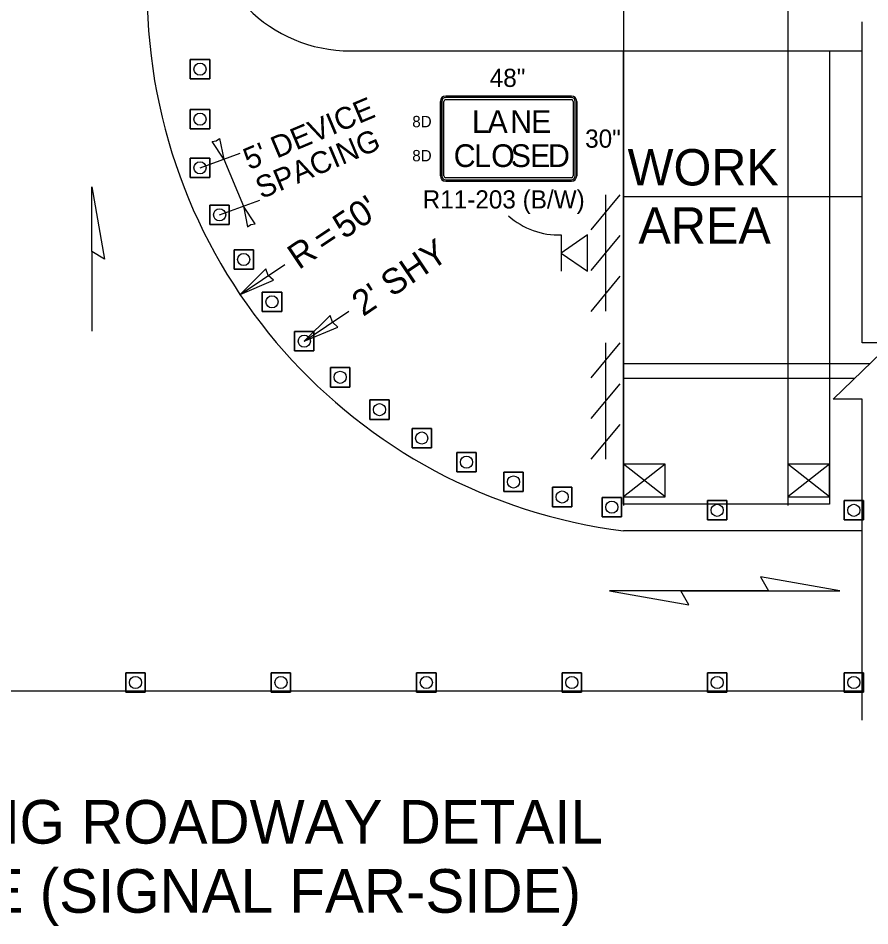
# Model space of a CAD drawing. Extents: x 99979.8 to 100075.7, y 99995 to 100010.7.
# Drawn here: x 100048.053 to 100050.396, y 100006.124 to 100008.621 of the extents above; entities that cross this region are included whole.
import ezdxf

# ---------------------------------------------------------------- set-up
doc = ezdxf.new("R2010")
doc.units = 0
for name, color, linetype in [('RD_ED_ShoulderPavedEdge', 7, 'Continuous'), ('RD_MK_LineDblYellowCenter', 7, 'Continuous'), ('RD_MK_LineEdgeWhite', 7, 'Continuous'), ('RD_MK_LineEdgeWhiteNew', 7, 'Continuous'), ('SH_DE_DetailHeading2Text', 7, 'Continuous'), ('TR_SN_ConstructionSigns', 7, 'Continuous'), ('TR_WZ_BarricadeType3', 7, 'Continuous'), ('TR_WZ_PortableSignMount5ftMinBlk-Wht', 7, 'Continuous'), ('TR_WZ_PortableSignMountBlk-Wht', 7, 'Continuous'), ('TR_WZ_TrafficCone', 7, 'Continuous'), ('TR_WZ_WorkAreaLabel', 7, 'Continuous'), ('TR_WZ_WorkZoneDetails', 7, 'Continuous'), ('TR_WZ_WorkZoneTextCurrent', 7, 'Continuous')]:
    doc.layers.add(name, color=color, linetype=linetype)

msp = doc.modelspace()

# ---------------------------------------------------------------- linework, layer by layer
at = {"layer": 'RD_ED_ShoulderPavedEdge'}
for p, q in [((100048.9675, 100008.5305), (100050.375, 100008.5305)), ((100045.375, 100006.7704), (100050.375, 100006.7704))]:
    msp.add_line(p, q, dxfattribs=at)
msp.add_arc((100048.9675, 100008.9304), 0.4, 180, 270, dxfattribs=at)
at = {"layer": 'RD_MK_LineDblYellowCenter'}
for p, q in [((100049.7179, 100007.6704), (100050.3957, 100007.6704)), ((100049.7179, 100007.6305), (100050.3543, 100007.6305))]:
    msp.add_line(p, q, dxfattribs=at)
at = {"layer": 'RD_MK_LineEdgeWhite'}
for p, q in [((100049.7179, 100008.1305), (100050.375, 100008.1305)), ((100050.375, 100007.2105), (100049.7179, 100007.2105))]:
    msp.add_line(p, q, dxfattribs=at)
at = {"layer": 'RD_MK_LineEdgeWhiteNew'}
msp.add_arc((100049.9075, 100008.6984), 1.5, 180.3046, 262.7399, dxfattribs=at)
at = {"layer": 'TR_SN_ConstructionSigns'}
for p, q in [((100049.229, 100008.4064), (100049.5747, 100008.4064)), ((100049.5747, 100008.4064), (100049.229, 100008.4064)), ((100049.5747, 100008.4064), (100049.229, 100008.4064)), ((100049.5747, 100008.4025), (100049.229, 100008.4025)), ((100049.2144, 100008.1867), (100049.2144, 100008.3918)), ((100049.2144, 100008.3918), (100049.2144, 100008.1867)), ((100049.2144, 100008.3918), (100049.2144, 100008.1867)), ((100049.2183, 100008.3918), (100049.2183, 100008.1867)), ((100049.2241, 100008.1867), (100049.2241, 100008.3918)), ((100049.229, 100008.3967), (100049.5747, 100008.3967)), ((100049.5796, 100008.3918), (100049.5796, 100008.1867)), ((100049.5855, 100008.1867), (100049.5855, 100008.3918)), ((100049.5894, 100008.3918), (100049.5894, 100008.1867)), ((100049.5894, 100008.1867), (100049.5894, 100008.3918)), ((100049.5894, 100008.1867), (100049.5894, 100008.3918)), ((100049.5747, 100008.1818), (100049.229, 100008.1818)), ((100049.229, 100008.176), (100049.5747, 100008.176)), ((100049.5747, 100008.1721), (100049.229, 100008.1721)), ((100049.229, 100008.1721), (100049.5747, 100008.1721)), ((100049.229, 100008.1721), (100049.5747, 100008.1721))]:
    msp.add_line(p, q, dxfattribs=at)
for centre, radius, start, end in [((100049.229, 100008.3918), 0.0146, 90, 180), ((100049.229, 100008.3918), 0.0146, 90, 180), ((100049.229, 100008.3918), 0.0146, 90, 180), ((100049.229, 100008.3918), 0.0107, 90, 180), ((100049.5747, 100008.3918), 0.0146, 0, 90), ((100049.5747, 100008.3918), 0.0146, 0, 90), ((100049.5747, 100008.3918), 0.0146, 0, 90), ((100049.5747, 100008.3918), 0.0107, 0, 90), ((100049.229, 100008.3918), 0.00488, 90, 180), ((100049.5747, 100008.3918), 0.00488, 0, 90), ((100049.229, 100008.1867), 0.0146, 180, 270), ((100049.229, 100008.1867), 0.0146, 180, 270), ((100049.229, 100008.1867), 0.0146, 180, 270), ((100049.229, 100008.1867), 0.0107, 180, 270), ((100049.229, 100008.1867), 0.00488, 180, 270), ((100049.5747, 100008.1867), 0.0107, 270, 0), ((100049.5747, 100008.1867), 0.00488, 270, 0), ((100049.5747, 100008.1867), 0.0146, 270, 0), ((100049.5747, 100008.1867), 0.0146, 270, 0), ((100049.5747, 100008.1867), 0.0146, 270, 0)]:
    msp.add_arc(centre, radius, start, end, dxfattribs=at)
at = {"layer": 'TR_WZ_BarricadeType3'}
for p, q in [((100049.6287, 100008.0385), (100049.7087, 100008.135)), ((100049.6687, 100008.1345), (100049.6687, 100007.8145)), ((100049.6287, 100007.9263), (100049.7087, 100008.0228)), ((100049.6287, 100007.8141), (100049.7087, 100007.9106)), ((100049.6294, 100007.6318), (100049.7087, 100007.7273)), ((100049.669, 100007.7273), (100049.669, 100007.4073)), ((100049.6294, 100007.5195), (100049.7087, 100007.6151)), ((100049.6294, 100007.4073), (100049.7087, 100007.5029))]:
    msp.add_line(p, q, dxfattribs=at)
at = {"layer": 'TR_WZ_PortableSignMount5ftMinBlk-Wht'}
for p, q in [((100049.7179, 100007.4184), (100049.7179, 100007.2805)), ((100050.17, 100007.4184), (100050.17, 100007.2805)), ((100049.833, 100007.3046), (100049.7179, 100007.3942)), ((100049.833, 100007.3942), (100049.7179, 100007.3046)), ((100050.285, 100007.3046), (100050.17, 100007.3942)), ((100050.285, 100007.3942), (100050.17, 100007.3046)), ((100049.7755, 100007.3494), (100049.7755, 100007.3494)), ((100049.7756, 100007.3493), (100049.7756, 100007.3493)), ((100050.2275, 100007.3494), (100050.2275, 100007.3494)), ((100050.2277, 100007.3493), (100050.2277, 100007.3493))]:
    msp.add_line(p, q, dxfattribs=at)
for points in [[(100049.833, 100007.3046), (100049.833, 100007.3942), (100049.7179, 100007.3942), (100049.7179, 100007.3046)], [(100050.285, 100007.3046), (100050.285, 100007.3942), (100050.17, 100007.3942), (100050.17, 100007.3046)]]:
    msp.add_lwpolyline(points, close=True, dxfattribs=at)
at = {"layer": 'TR_WZ_PortableSignMountBlk-Wht'}
msp.add_line((100049.5469, 100008.0245), (100049.5469, 100007.9245), dxfattribs=at)
msp.add_lwpolyline([(100049.5469, 100007.9746), (100049.6187, 100007.9245), (100049.6187, 100008.0245)], close=True, dxfattribs=at)
at = {"layer": 'TR_WZ_TrafficCone'}
for points in [[(100048.5798, 100008.5068), (100048.5264, 100008.5068), (100048.5264, 100008.4535), (100048.5798, 100008.4535), (100048.5798, 100008.5068)], [(100048.5798, 100008.4535), (100048.5264, 100008.4535), (100048.5264, 100008.5068), (100048.5798, 100008.5068), (100048.5798, 100008.4535)], [(100048.5798, 100008.3696), (100048.5264, 100008.3696), (100048.5264, 100008.3163), (100048.5798, 100008.3163), (100048.5798, 100008.3696)], [(100048.5798, 100008.3163), (100048.5264, 100008.3163), (100048.5264, 100008.3696), (100048.5798, 100008.3696), (100048.5798, 100008.3163)], [(100048.5798, 100008.2358), (100048.5264, 100008.2358), (100048.5264, 100008.1825), (100048.5798, 100008.1825), (100048.5798, 100008.2358)], [(100048.5798, 100008.1825), (100048.5264, 100008.1825), (100048.5264, 100008.2358), (100048.5798, 100008.2358), (100048.5798, 100008.1825)], [(100048.6337, 100008.1066), (100048.5804, 100008.1066), (100048.5804, 100008.0532), (100048.6337, 100008.0532), (100048.6337, 100008.1066)], [(100048.6337, 100008.0532), (100048.5804, 100008.0532), (100048.5804, 100008.1066), (100048.6337, 100008.1066), (100048.6337, 100008.0532)], [(100048.6999, 100007.9832), (100048.6466, 100007.9832), (100048.6466, 100007.9299), (100048.6999, 100007.9299), (100048.6999, 100007.9832)], [(100048.6999, 100007.9299), (100048.6466, 100007.9299), (100048.6466, 100007.9832), (100048.6999, 100007.9832), (100048.6999, 100007.9299)], [(100048.7778, 100007.8669), (100048.7244, 100007.8669), (100048.7244, 100007.8136), (100048.7778, 100007.8136), (100048.7778, 100007.8669)], [(100048.7778, 100007.8136), (100048.7244, 100007.8136), (100048.7244, 100007.8669), (100048.7778, 100007.8669), (100048.7778, 100007.8136)], [(100048.8666, 100007.7587), (100048.8132, 100007.7587), (100048.8132, 100007.7053), (100048.8666, 100007.7053), (100048.8666, 100007.7587)], [(100048.8666, 100007.7053), (100048.8132, 100007.7053), (100048.8132, 100007.7587), (100048.8666, 100007.7587), (100048.8666, 100007.7053)], [(100048.9655, 100007.6596), (100048.9121, 100007.6596), (100048.9121, 100007.6062), (100048.9655, 100007.6062), (100048.9655, 100007.6596)], [(100048.9655, 100007.6062), (100048.9121, 100007.6062), (100048.9121, 100007.6596), (100048.9655, 100007.6596), (100048.9655, 100007.6062)], [(100049.0735, 100007.5705), (100049.0202, 100007.5705), (100049.0202, 100007.5172), (100049.0735, 100007.5172), (100049.0735, 100007.5705)], [(100049.0735, 100007.5172), (100049.0202, 100007.5172), (100049.0202, 100007.5705), (100049.0735, 100007.5705), (100049.0735, 100007.5172)], [(100049.1897, 100007.4924), (100049.1364, 100007.4924), (100049.1364, 100007.4391), (100049.1897, 100007.4391), (100049.1897, 100007.4924)], [(100049.1897, 100007.4391), (100049.1364, 100007.4391), (100049.1364, 100007.4924), (100049.1897, 100007.4924), (100049.1897, 100007.4391)], [(100049.3129, 100007.426), (100049.2596, 100007.426), (100049.2596, 100007.3726), (100049.3129, 100007.3726), (100049.3129, 100007.426)], [(100049.3129, 100007.3726), (100049.2596, 100007.3726), (100049.2596, 100007.426), (100049.3129, 100007.426), (100049.3129, 100007.3726)], [(100049.442, 100007.3718), (100049.3887, 100007.3718), (100049.3887, 100007.3184), (100049.442, 100007.3184), (100049.442, 100007.3718)], [(100049.442, 100007.3184), (100049.3887, 100007.3184), (100049.3887, 100007.3718), (100049.442, 100007.3718), (100049.442, 100007.3184)], [(100049.5757, 100007.3304), (100049.5224, 100007.3304), (100049.5224, 100007.2771), (100049.5757, 100007.2771), (100049.5757, 100007.3304)], [(100049.5757, 100007.2771), (100049.5224, 100007.2771), (100049.5224, 100007.3304), (100049.5757, 100007.3304), (100049.5757, 100007.2771)], [(100049.7129, 100007.3022), (100049.6595, 100007.3022), (100049.6595, 100007.2489), (100049.7129, 100007.2489), (100049.7129, 100007.3022)], [(100049.7129, 100007.2489), (100049.6595, 100007.2489), (100049.6595, 100007.3022), (100049.7129, 100007.3022), (100049.7129, 100007.2489)], [(100049.949, 100007.2938), (100050.0023, 100007.2938), (100050.0023, 100007.2405), (100049.949, 100007.2405), (100049.949, 100007.2938)], [(100049.949, 100007.2405), (100050.0023, 100007.2405), (100050.0023, 100007.2938), (100049.949, 100007.2938), (100049.949, 100007.2405)], [(100050.325, 100007.2938), (100050.3783, 100007.2938), (100050.3783, 100007.2405), (100050.325, 100007.2405), (100050.325, 100007.2938)], [(100050.325, 100007.2405), (100050.3783, 100007.2405), (100050.3783, 100007.2938), (100050.325, 100007.2938), (100050.325, 100007.2405)], [(100048.349, 100006.8204), (100048.4023, 100006.8204), (100048.4023, 100006.7671), (100048.349, 100006.7671), (100048.349, 100006.8204)], [(100048.349, 100006.7671), (100048.4023, 100006.7671), (100048.4023, 100006.8204), (100048.349, 100006.8204), (100048.349, 100006.7671)], [(100048.749, 100006.8204), (100048.8023, 100006.8204), (100048.8023, 100006.7671), (100048.749, 100006.7671), (100048.749, 100006.8204)], [(100048.749, 100006.7671), (100048.8023, 100006.7671), (100048.8023, 100006.8204), (100048.749, 100006.8204), (100048.749, 100006.7671)], [(100049.149, 100006.8204), (100049.2023, 100006.8204), (100049.2023, 100006.7671), (100049.149, 100006.7671), (100049.149, 100006.8204)], [(100049.149, 100006.7671), (100049.2023, 100006.7671), (100049.2023, 100006.8204), (100049.149, 100006.8204), (100049.149, 100006.7671)], [(100049.549, 100006.8204), (100049.6023, 100006.8204), (100049.6023, 100006.7671), (100049.549, 100006.7671), (100049.549, 100006.8204)], [(100049.549, 100006.7671), (100049.6023, 100006.7671), (100049.6023, 100006.8204), (100049.549, 100006.8204), (100049.549, 100006.7671)], [(100049.949, 100006.8204), (100050.0023, 100006.8204), (100050.0023, 100006.7671), (100049.949, 100006.7671), (100049.949, 100006.8204)], [(100049.949, 100006.7671), (100050.0023, 100006.7671), (100050.0023, 100006.8204), (100049.949, 100006.8204), (100049.949, 100006.7671)], [(100050.325, 100006.8204), (100050.3783, 100006.8204), (100050.3783, 100006.7671), (100050.325, 100006.7671), (100050.325, 100006.8204)], [(100050.325, 100006.7671), (100050.3783, 100006.7671), (100050.3783, 100006.8204), (100050.325, 100006.8204), (100050.325, 100006.7671)]]:
    msp.add_lwpolyline(points, dxfattribs=at)
for centre in [(100048.5531, 100008.4801), (100048.5531, 100008.3429), (100048.5531, 100008.2091), (100048.607, 100008.0799), (100048.6732, 100007.9566), (100048.7511, 100007.8402), (100048.8399, 100007.732), (100048.9388, 100007.6329), (100049.0468, 100007.5439), (100049.163, 100007.4658), (100049.2862, 100007.3993), (100049.4153, 100007.3451), (100049.5491, 100007.3037), (100049.6862, 100007.2755), (100049.9757, 100007.2671), (100050.3517, 100007.2671), (100048.3757, 100006.7938), (100048.7757, 100006.7938), (100049.1757, 100006.7938), (100049.5757, 100006.7938), (100049.9757, 100006.7938), (100050.3517, 100006.7938)]:
    msp.add_circle(centre, 0.0167, dxfattribs=at)
at = {"layer": 'TR_WZ_WorkZoneDetails'}
for p, q in [((100049.7179, 100008.6504), (100049.7179, 100007.4184)), ((100050.17, 100008.6504), (100050.17, 100007.4184)), ((100048.5532, 100008.2091), (100048.6637, 100008.249)), ((100048.6184, 100008.2327), (100048.6723, 100008.1035)), ((100048.6071, 100008.0799), (100048.7176, 100008.1198)), ((100048.2552, 100007.9784), (100048.2552, 100007.7594)), ((100048.6632, 100007.8606), (100048.786, 100007.9433)), ((100048.8399, 100007.7319), (100048.9628, 100007.8146)), ((100050.117, 100007.0455), (100049.8759, 100007.0455)), ((100049.8759, 100007.0455), (100050.117, 100007.0455))]:
    msp.add_line(p, q, dxfattribs=at)
msp.add_lwpolyline([(100050.375, 100006.6904), (100050.375, 100007.573), (100050.295, 100007.573), (100050.455, 100007.7279), (100050.375, 100007.7279), (100050.375, 100008.6105)], dxfattribs=at)
for points in [[(100050.285, 100008.5305), (100050.285, 100007.2838), (100049.7179, 100007.2838), (100049.7179, 100007.2838), (100049.7179, 100007.2838), (100049.7179, 100007.2838), (100049.7179, 100007.2838), (100049.7179, 100007.2838), (100049.7179, 100007.2838), (100049.7179, 100007.4226), (100049.7179, 100007.5672), (100049.7179, 100007.732), (100049.7179, 100007.9566), (100049.7179, 100008.2091), (100049.7179, 100008.5305)], [(100048.6184, 100008.2327), (100048.5861, 100008.2811), (100048.5974, 100008.283), (100048.6068, 100008.2897)], [(100048.2552, 100008.157), (100048.2903, 100007.9582), (100048.2552, 100007.9784)], [(100048.6723, 100008.1035), (100048.684, 100008.0464), (100048.6933, 100008.0532), (100048.7047, 100008.0551)], [(100048.6632, 100007.8606), (100048.7555, 100007.8996), (100048.7409, 100007.913), (100048.7339, 100007.9315)], [(100048.8399, 100007.7319), (100048.9322, 100007.7709), (100048.9177, 100007.7843), (100048.9107, 100007.8028)], [(100050.3136, 100007.0455), (100050.0947, 100007.084), (100050.117, 100007.0455)], [(100049.6794, 100007.0455), (100049.8982, 100007.0069), (100049.8759, 100007.0455)]]:
    msp.add_lwpolyline(points, close=True, dxfattribs=at)
msp.add_arc((100049.5394, 100008.2304), 0.206, 228.1009, 272.0686, dxfattribs=at)

# ---------------------------------------------------------------- texts
at = {"layer": 'SH_DE_DetailHeading2Text'}
for s, p in [('UNSIGNALIZED INTERSECTING ROADWAY DETAIL', (100045.7563, 100006.3504)), ('SAME SIDE AS LANE CLOSURE (SIGNAL FAR-SIDE)', (100045.6509, 100006.1604))]:
    msp.add_text(s, height=0.12, rotation=360, dxfattribs=at).set_placement(p)
at = {"layer": 'TR_SN_ConstructionSigns'}
for s, p in [('48"', (100049.35, 100008.4314)), ('30"', (100049.6125, 100008.2643)), ('R11-203 (B/W)', (100049.1655, 100008.0971))]:
    msp.add_text(s, height=0.05, rotation=360, dxfattribs=at).set_placement(p)
for s, height, p in [('8D', 0.03125, (100049.1369, 100008.3205)), ('L', 0.0625, (100049.3013, 100008.3049)), ('A', 0.0625, (100049.3438, 100008.3049)), ('N', 0.0625, (100049.4063, 100008.3049)), ('E', 0.0625, (100049.4638, 100008.3049)), ('C', 0.0625, (100049.2509, 100008.2111)), ('O', 0.0625, (100049.3541, 100008.2111)), ('S', 0.0625, (100049.4078, 100008.2111)), ('8D', 0.03125, (100049.1369, 100008.2268)), ('L', 0.0625, (100049.3072, 100008.2111)), ('E', 0.0625, (100049.4609, 100008.2111)), ('D', 0.0625, (100049.5103, 100008.2111))]:
    msp.add_text(s, height=height, dxfattribs=at).set_placement(p)
at = {"layer": 'TR_WZ_WorkAreaLabel'}
for s, p in [('WORK', (100049.7294, 100008.1605)), ('AREA', (100049.7591, 100008.0004))]:
    msp.add_text(s, height=0.1, dxfattribs=at).set_placement(p)
at = {"layer": 'TR_WZ_WorkZoneTextCurrent'}
for s, height, rotation, p in [("5' DEVICE", 0.06, 22.8888, (100048.6884, 100008.202)), ('SPACING', 0.06, 22.8888, (100048.7219, 100008.1226)), ("50'", 0.07, 33.9451, (100048.9492, 100008.011)), ('=', 0.07, 33.9451, (100048.8942, 100007.9739)), ('R', 0.07, 33.9451, (100048.8248, 100007.9272)), ("2' SHY", 0.07, 33.9451, (100049.0016, 100007.7985))]:
    msp.add_text(s, height=height, rotation=rotation, dxfattribs=at).set_placement(p)

doc.saveas('drawing.dxf')
